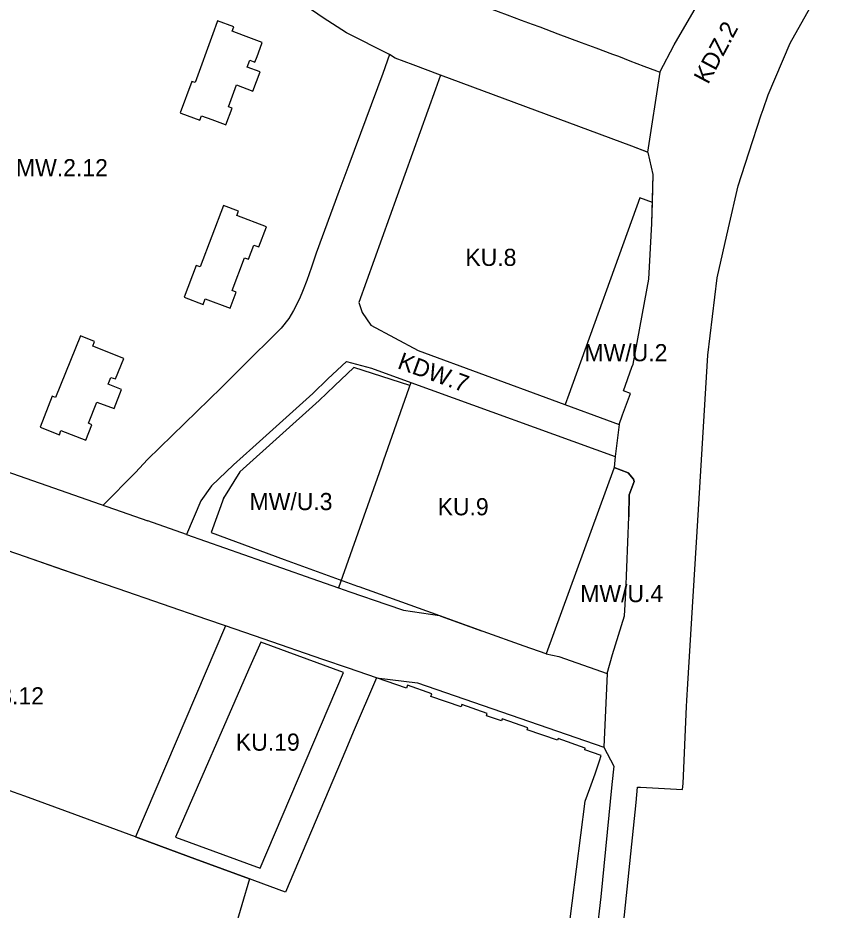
# Model space of a CAD drawing. Extents: x 7428239 to 7429836, y 5549133 to 5550853.
# Drawn here: x 7429316.4 to 7429550.9, y 5549745.6 to 5550005.5 of the extents above; entities that cross this region are included whole.
import ezdxf

# ---------------------------------------------------------------- set-up
doc = ezdxf.new("R2010")
doc.units = 0
for name, color, linetype in [('LIN_linia regulacyjna', 7, 'Continuous'), ('LIN_linie rozgraniczające', 7, 'Continuous'), ('LIN_nieprzekraczalna linia zabudowy', 7, 'Continuous'), ('LIN_obowiązująca linia zabudowy', 7, 'Continuous'), ('TXT_Oznaczenia Przeznaczenia', 7, 'Continuous')]:
    doc.layers.add(name, color=color, linetype=linetype)

msp = doc.modelspace()

# ---------------------------------------------------------------- linework, layer by layer
at = {"layer": 'LIN_linia regulacyjna'}
msp.add_lwpolyline([(7429383.84, 5549754.68), (7429367.89, 5549760.56), (7429360.9, 5549763.13), (7429350.66, 5549766.9), (7429332.99, 5549773.42), (7429318.45, 5549778.77), (7429315.16, 5549779.99), (7429235.41, 5549809.37), (7429221.85, 5549817.44), (7429207.39, 5549820.5), (7429189.98, 5549824.19), (7429183.11, 5549825.65)], dxfattribs=at)
at = {"layer": 'LIN_linie rozgraniczające'}
for p, q in [((7429541.25, 5549998.1), (7429550.86, 5550015.24)), ((7429431.47, 5549991.78), (7429426.24, 5549993.73)), ((7429439.42, 5549988.82), (7429431.47, 5549991.78)), ((7429503.29, 5549989.64), (7429499.74, 5549966.36)), ((7429439.42, 5549988.82), (7429437.96, 5549984.73)), ((7429495.18, 5549968.05), (7429439.42, 5549988.82)), ((7429437.96, 5549984.73), (7429415.68, 5549922.55)), ((7429523.31, 5549944.31), (7429526.1, 5549956.54)), ((7429497.45, 5549953.02), (7429476.78, 5549895.75)), ((7429520.01, 5549929.79), (7429523.31, 5549944.31)), ((7429517.3, 5549907.25), (7429520.01, 5549929.79)), ((7429415.68, 5549922.55), (7429416.64, 5549919.69)), ((7429416.64, 5549919.69), (7429419.17, 5549915.97)), ((7429419.17, 5549915.97), (7429432.98, 5549908.58)), ((7429432.98, 5549908.58), (7429491.44, 5549887.03)), ((7429514.16, 5549855.88), (7429517.3, 5549907.25)), ((7429412.08, 5549905.42), (7429406.7, 5549900.31)), ((7429412.08, 5549905.42), (7429419.37, 5549903.43)), ((7429419.37, 5549903.43), (7429430.85, 5549899.25)), ((7429406.7, 5549900.31), (7429402.26, 5549896.08)), ((7429430.85, 5549899.25), (7429422.88, 5549876.62)), ((7429430.85, 5549899.25), (7429490.35, 5549877.67)), ((7429402.26, 5549896.08), (7429384.79, 5549880.36)), ((7429476.78, 5549895.75), (7429475.72, 5549892.83)), ((7429384.79, 5549880.36), (7429379.16, 5549875.29)), ((7429379.16, 5549875.29), (7429372.79, 5549869.13)), ((7429422.88, 5549876.62), (7429422.17, 5549874.61)), ((7429312.94, 5549873.44), (7429354.21, 5549858.95)), ((7429422.17, 5549874.61), (7429409.78, 5549839.42)), ((7429372.79, 5549869.13), (7429369.66, 5549864.78)), ((7429369.66, 5549864.78), (7429365.55, 5549854.96)), ((7429365.55, 5549854.96), (7429354.21, 5549858.95)), ((7429365.55, 5549854.96), (7429393.14, 5549845.26)), ((7429512.83, 5549833.81), (7429514.16, 5549855.88)), ((7429332.07, 5549843.85), (7429316.41, 5549849.25)), ((7429393.14, 5549845.26), (7429401.97, 5549842.17)), ((7429339.9, 5549841.15), (7429332.07, 5549843.85)), ((7429401.97, 5549842.17), (7429409.78, 5549839.42)), ((7429341.06, 5549840.75), (7429339.9, 5549841.15)), ((7429345.57, 5549839.2), (7429341.06, 5549840.75)), ((7429371.43, 5549830.28), (7429345.57, 5549839.2)), ((7429409.78, 5549839.42), (7429413.11, 5549838.29)), ((7429413.11, 5549838.29), (7429423.79, 5549834.65)), ((7429376.87, 5549828.41), (7429371.43, 5549830.28)), ((7429387.85, 5549824.62), (7429376.87, 5549828.41)), ((7429405.25, 5549818.62), (7429387.85, 5549824.62)), ((7429412.7, 5549816.06), (7429405.25, 5549818.62)), ((7429420.78, 5549813.28), (7429412.7, 5549816.06)), ((7429420.78, 5549813.28), (7429414.07, 5549797.45)), ((7429420.78, 5549813.28), (7429432.76, 5549811.78)), ((7429432.76, 5549811.78), (7429487.03, 5549793.03)), ((7429510.11, 5549782.51), (7429511.07, 5549804.92)), ((7429414.07, 5549797.45), (7429411.87, 5549792.25)), ((7429411.87, 5549792.25), (7429394.34, 5549750.81)), ((7429487.03, 5549793.03), (7429489.93, 5549787.53)), ((7429509.94, 5549780.72), (7429510.11, 5549782.51)), ((7429497.66, 5549781.39), (7429509.94, 5549780.72)), ((7429492.21, 5549735.89), (7429496.38, 5549776.96)), ((7429383.84, 5549754.68), (7429374.1, 5549721.36)), ((7429385.38, 5549754.11), (7429383.84, 5549754.68)), ((7429394.34, 5549750.81), (7429385.38, 5549754.11))]:
    msp.add_line(p, q, dxfattribs=at)
for points in [[(7429503.29, 5549989.64), (7429507.45, 5549997.62), (7429514.02, 5550008.76), (7429523.15, 5550023.38), (7429528.7, 5550031.36)], [(7429417.93, 5550027.68), (7429421.87, 5550022.5), (7429439.14, 5550014.31), (7429443.05, 5550012.66), (7429446.38, 5550011.19), (7429448.41, 5550010.38), (7429453.35, 5550008.35), (7429456.2, 5550007.29), (7429458.89, 5550006.3), (7429462.96, 5550004.84), (7429466.18, 5550003.65), (7429468.38, 5550002.81), (7429473.58, 5550000.83), (7429480.45, 5549998.32), (7429484.71, 5549996.72), (7429489.55, 5549994.94), (7429491.29, 5549994.27), (7429494.59, 5549992.97), (7429498.65, 5549991.43), (7429502.37, 5549990.02), (7429503.29, 5549989.64)], [(7429426.24, 5549993.73), (7429424.64, 5549994.76), (7429412.09, 5550001.09), (7429405.27, 5550005.47), (7429400.38, 5550008.88), (7429398.57, 5550010.23), (7429394.76, 5550013.85)], [(7429532.84, 5549977.27), (7429533.36, 5549978.78), (7429534.84, 5549983.04), (7429541.25, 5549998.1)], [(7429424.64, 5549994.76), (7429422.69, 5549989.27), (7429412.75, 5549962.67), (7429409.87, 5549954.9), (7429403.3, 5549936.93), (7429401.95, 5549932.84), (7429401.25, 5549930.9), (7429400.55, 5549928.95), (7429399.46, 5549926.3), (7429398.37, 5549923.65), (7429396.71, 5549920.21), (7429395.29, 5549917.86), (7429393.05, 5549915.07), (7429390.51, 5549912.59), (7429383.86, 5549905.98), (7429375.69, 5549897.85), (7429354.12, 5549876.83), (7429350.64, 5549873.1), (7429341.26, 5549863.5)], [(7429526.1, 5549956.54), (7429529.23, 5549966.16), (7429532.84, 5549977.27)], [(7429491.44, 5549887.03), (7429492.47, 5549889.84), (7429494.77, 5549896.08), (7429492.73, 5549896.86), (7429495.14, 5549903.74), (7429495.53, 5549904.63), (7429500.08, 5549929.37), (7429501.01, 5549945.57), (7429501.15, 5549951.65), (7429501.34, 5549959.88), (7429499.94, 5549966.28), (7429499.74, 5549966.36)], [(7429499.74, 5549966.36), (7429495.18, 5549968.05)], [(7429501.15, 5549951.65), (7429497.45, 5549953.02)], [(7429491.44, 5549887.03), (7429490.35, 5549877.67), (7429489.98, 5549874.51)], [(7429489.98, 5549874.51), (7429489.88, 5549874.24), (7429470.27, 5549820.27)], [(7429489.98, 5549874.51), (7429494.13, 5549872.97), (7429495.66, 5549871.14), (7429495.82, 5549870.4), (7429494.34, 5549866.55), (7429494.3, 5549860.16)], [(7429487.98, 5549814.53), (7429489.58, 5549820.06), (7429493.04, 5549831.3), (7429493.41, 5549838.03), (7429494.3, 5549860.16)], [(7429423.79, 5549834.65), (7429428.69, 5549832.98)], [(7429511.07, 5549804.92), (7429511.18, 5549806.69), (7429511.47, 5549811.55), (7429512.83, 5549833.81)], [(7429428.69, 5549832.98), (7429439.2, 5549831.36), (7429451.81, 5549826.81), (7429463.7, 5549822.54)], [(7429376.87, 5549828.41), (7429350.66, 5549766.9), (7429360.9, 5549763.13), (7429367.89, 5549760.56), (7429383.84, 5549754.68)], [(7429463.7, 5549822.54), (7429470.13, 5549820.3), (7429470.27, 5549820.27)], [(7429470.27, 5549820.27), (7429473.87, 5549819.44), (7429487.98, 5549814.53), (7429487.03, 5549793.03)], [(7429489.93, 5549787.53), (7429489.37, 5549782.19)], [(7429489.37, 5549782.19), (7429486.1, 5549749.51), (7429484.91, 5549738.63), (7429483.01, 5549718.14), (7429474.16, 5549684.69), (7429476.09, 5549678.57), (7429469.44, 5549659.48), (7429459.97, 5549633.44), (7429459.77, 5549632.89), (7429454.38, 5549618.41), (7429430.39, 5549556.05), (7429426.47, 5549553.73)], [(7429496.38, 5549776.96), (7429496.83, 5549781.43), (7429497.66, 5549781.39)]]:
    msp.add_lwpolyline(points, dxfattribs=at)
at = {"layer": 'LIN_nieprzekraczalna linia zabudowy'}
for points in [[(7429499.94, 5549966.28), (7429495.18, 5549968.05), (7429439.42, 5549988.82)], [(7429491.44, 5549887.03), (7429492.47, 5549889.84), (7429494.77, 5549896.08), (7429492.73, 5549896.86), (7429495.14, 5549903.74), (7429495.53, 5549904.63), (7429500.08, 5549929.37), (7429501.01, 5549945.57), (7429501.34, 5549959.88), (7429499.94, 5549966.28)], [(7429430.57, 5549898.44), (7429414.23, 5549903.6), (7429408.63, 5549898.28), (7429404.16, 5549894.02), (7429381.07, 5549873.24), (7429376.3, 5549865.58), (7429376.37, 5549865.77), (7429372.65, 5549855.56), (7429393.93, 5549847.67), (7429415.3, 5549839.99), (7429415.73, 5549839.83), (7429439.2, 5549831.36), (7429439.59, 5549831.22), (7429451.41, 5549826.94), (7429451.81, 5549826.81), (7429463.7, 5549822.54), (7429470.13, 5549820.3), (7429470.27, 5549820.27), (7429473.87, 5549819.44), (7429487.98, 5549814.53), (7429489.58, 5549820.06), (7429493.04, 5549831.3), (7429493.41, 5549838.03), (7429494.3, 5549860.16), (7429494.34, 5549866.55), (7429495.82, 5549870.4), (7429495.66, 5549871.14), (7429494.13, 5549872.97), (7429489.98, 5549874.51)], [(7429376.87, 5549828.41), (7429371.43, 5549830.28), (7429345.57, 5549839.2), (7429329.74, 5549844.65), (7429316.41, 5549849.25), (7429248.77, 5549872.41), (7429233.7, 5549877.99)], [(7429411.2, 5549814.83), (7429387.11, 5549823.65), (7429383.59, 5549815.59), (7429362.32, 5549766.87), (7429386.99, 5549757.78), (7429411.22, 5549814.82)], [(7429476.56, 5549737.72), (7429481.57, 5549777.29), (7429482.89, 5549781.01), (7429484.46, 5549785.31), (7429485.74, 5549789.09), (7429486.25, 5549790.65), (7429481.44, 5549792.32), (7429481.6, 5549792.76), (7429473.7, 5549795.59), (7429473.51, 5549795.06), (7429464.71, 5549798.1), (7429464.92, 5549798.68), (7429457.46, 5549801.35), (7429457.22, 5549800.69), (7429452.82, 5549802.21), (7429453.04, 5549802.83), (7429445.68, 5549805.45), (7429445.43, 5549804.76), (7429436.62, 5549807.81), (7429436.9, 5549808.6), (7429429.86, 5549811.12), (7429429.55, 5549810.25), (7429420.78, 5549813.28)]]:
    msp.add_lwpolyline(points, dxfattribs=at)
at = {"layer": 'LIN_obowiązująca linia zabudowy'}
for points in [[(7429380.09, 5549985.93), (7429384.84, 5549984.14), (7429386.91, 5549989.78), (7429383.22, 5549991.15), (7429383.94, 5549993.1), (7429385.43, 5549992.56), (7429386.07, 5549994.25), (7429387.46, 5549997.97), (7429387.58, 5549998.29), (7429382.07, 5550000.36), (7429378.85, 5550001.57), (7429379.32, 5550002.83), (7429374.53, 5550004.63), (7429374.43, 5550004.35), (7429373.15, 5550000.84), (7429367.99, 5549986.68), (7429367.06, 5549986.96), (7429363.68, 5549977.8), (7429363.86, 5549977.73), (7429367.51, 5549976.35), (7429369.42, 5549975.63), (7429369.9, 5549976.94), (7429372.93, 5549975.82), (7429376.74, 5549974.4), (7429376.98, 5549974.31), (7429378.82, 5549979.17), (7429377.76, 5549979.53)], [(7429368.34, 5549933.38), (7429364.82, 5549924.12), (7429370.38, 5549922.01), (7429370.99, 5549923.61), (7429378.2, 5549920.88), (7429379.99, 5549925.6), (7429378.81, 5549926.04), (7429382.43, 5549935.6), (7429383.57, 5549935.17), (7429385.13, 5549939.28), (7429386.53, 5549938.75), (7429388.76, 5549944.61), (7429380.14, 5549947.89), (7429380.63, 5549949.18), (7429376.27, 5549950.84), (7429369.47, 5549932.95)], [(7429339.42, 5549893.57), (7429344.45, 5549891.69), (7429346.58, 5549897.2), (7429342.69, 5549898.8), (7429343.48, 5549900.74), (7429344.84, 5549900.29), (7429347.24, 5549906.29), (7429338.23, 5549909.85), (7429338.73, 5549911.23), (7429334.69, 5549912.9), (7429327.41, 5549894.86), (7429326.45, 5549895.24), (7429322.91, 5549886.25), (7429328.5, 5549884.02), (7429328.96, 5549885.27), (7429336.16, 5549882.46), (7429337.94, 5549886.96), (7429336.98, 5549887.41)]]:
    msp.add_lwpolyline(points, close=True, dxfattribs=at)

# ---------------------------------------------------------------- texts
at = {"layer": 'TXT_Oznaczenia Przeznaczenia'}
for s, rotation, p in [('KDZ.2', 61.81, (7429517.35, 5549985.89)), ('KDW.7', 340.0724, (7429426.65, 5549903.48))]:
    msp.add_text(s, height=5, rotation=rotation, dxfattribs=at).set_placement(p)
for s, p in [('MW.2.12', (7429315.87, 5549959.32)), ('KU.8', (7429446.7, 5549933.22)), ('MW/U.2', (7429481.38, 5549905.45)), ('MW/U.3', (7429383.87, 5549862.1)), ('KU.9', (7429438.62, 5549860.59)), ('MW/U.4', (7429480.15, 5549835.29)), ('MW.3.12', (7429297.27, 5549805.51)), ('KU.19', (7429379.89, 5549792.03))]:
    msp.add_text(s, height=5, dxfattribs=at).set_placement(p)

doc.saveas('drawing.dxf')
